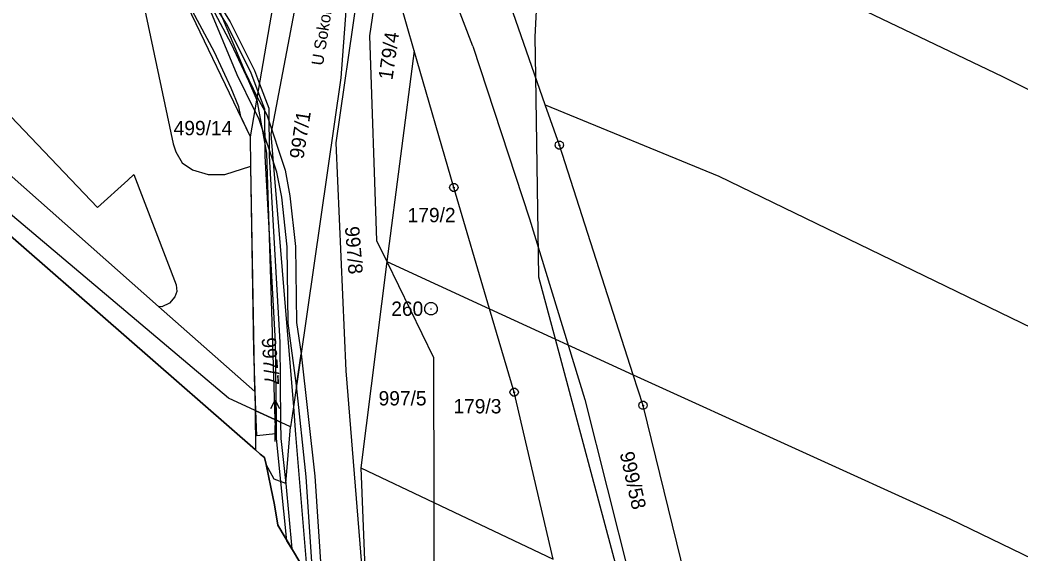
# Model space of a CAD drawing. Extents: x -755359 to -754474, y -1162585 to -1161655.
# Drawn here: x -755164.4 to -755045.7, y -1162495.1 to -1162431.7 of the extents above; entities that cross this region are included whole.
import ezdxf

# ---------------------------------------------------------------- set-up
doc = ezdxf.new("R2010")
doc.units = 0
for name, color, linetype in [('Vrstva 1', 7, 'Continuous'), ('Vrstva 11', 7, 'Continuous'), ('Vrstva 13', 7, 'Continuous'), ('Vrstva 2', 7, 'Continuous'), ('Vrstva 4', 7, 'Continuous'), ('Vrstva 6', 7, 'Continuous'), ('Vrstva 7', 7, 'Continuous'), ('Vrstva 8', 7, 'Continuous')]:
    doc.layers.add(name, color=color, linetype=linetype)

msp = doc.modelspace()

# ---------------------------------------------------------------- linework, layer by layer
at = {"layer": 'Vrstva 1'}
for p, q in [((-755208.3, -1162398.17), (-755155.2, -1162454)), ((-755137.03, -1162445.6), (-755132.49, -1162419.21)), ((-755125.01, -1162420.99), (-755126.31, -1162438.59)), ((-755102.04, -1162441.81), (-755109.07, -1162421.69)), ((-755121.39, -1162423.55), (-755122.9, -1162433.61)), ((-755117.59, -1162435.42), (-755120.28, -1162426.16)), ((-755047.73, -1162438.47), (-755073.63, -1162426.1)), ((-755149.93, -1162428.84), (-755146.21, -1162446.45)), ((-755137.03, -1162445.6), (-755145.43, -1162428.12)), ((-755122.9, -1162433.61), (-755122.06, -1162457.89)), ((-755117.59, -1162435.42), (-755120.84, -1162460.4)), ((-755112.89, -1162451.61), (-755117.59, -1162435.42)), ((-755126.31, -1162438.59), (-755131.94, -1162477.65)), ((-754970.94, -1162477.7), (-755047.73, -1162438.47)), ((-755177.29, -1162439.75), (-755147.93, -1162465.72)), ((-755102.04, -1162441.81), (-755081.44, -1162450.28)), ((-755100.37, -1162446.59), (-755102.04, -1162441.81)), ((-755178.31, -1162446.22), (-755136.42, -1162482.75)), ((-755146.21, -1162446.45), (-755145.88, -1162447.38)), ((-755136.97, -1162449.09), (-755137.03, -1162445.6)), ((-755091.61, -1162473.83), (-755100.37, -1162446.59)), ((-755139.64, -1162476.61), (-755175.06, -1162446.75)), ((-755145.88, -1162447.38), (-755145.15, -1162448.68)), ((-755145.15, -1162448.68), (-755143.92, -1162449.51)), ((-755151.6, -1162450.76), (-755150.88, -1162450.09)), ((-755150.88, -1162450.09), (-755145.86, -1162463.15)), ((-755143.92, -1162449.51), (-755142.03, -1162450.09)), ((-755142.03, -1162450.09), (-755140.07, -1162450.08)), ((-755140.07, -1162450.08), (-755136.97, -1162449.09)), ((-755136.53, -1162475.81), (-755136.97, -1162449.09)), ((-755155.2, -1162454), (-755151.6, -1162450.76)), ((-755081.44, -1162450.28), (-754979.63, -1162499.65)), ((-755108.65, -1162466), (-755112.89, -1162451.61)), ((-755122.06, -1162457.89), (-755120.84, -1162460.4)), ((-755120.84, -1162460.4), (-755123.93, -1162484.86)), ((-755120.84, -1162460.4), (-755108.65, -1162466)), ((-755120.84, -1162460.4), (-755115.31, -1162471.78)), ((-755145.86, -1162463.15), (-755145.78, -1162463.97)), ((-755145.78, -1162463.97), (-755146.01, -1162464.59)), ((-755146.63, -1162465.33), (-755147.53, -1162465.77)), ((-755146.01, -1162464.59), (-755146.63, -1162465.33)), ((-755147.53, -1162465.77), (-755147.93, -1162465.72)), ((-755147.93, -1162465.72), (-755136.53, -1162475.81)), ((-755108.65, -1162466), (-755091.61, -1162473.83)), ((-755105.74, -1162475.9), (-755108.65, -1162466)), ((-755115.31, -1162471.78), (-755115.28, -1162488.97)), ((-755091.61, -1162473.83), (-755054.02, -1162490.91)), ((-755090.44, -1162477.46), (-755091.61, -1162473.83)), ((-755136.53, -1162475.81), (-755136.49, -1162478.06)), ((-755101.11, -1162495.7), (-755105.74, -1162475.9)), ((-755136.49, -1162478.06), (-755139.64, -1162476.61)), ((-755083.94, -1162503.85), (-755090.44, -1162477.46)), ((-755132.28, -1162480), (-755136.49, -1162478.06)), ((-755136.49, -1162478.06), (-755136.42, -1162482.75)), ((-755131.94, -1162477.65), (-755132.28, -1162480)), ((-755132.85, -1162486.73), (-755132.28, -1162480)), ((-755136.42, -1162482.75), (-755135.89, -1162483.24)), ((-755135.89, -1162483.24), (-755135.35, -1162483.65)), ((-755135.35, -1162483.65), (-755135.17, -1162484.49)), ((-755135.17, -1162484.49), (-755134.62, -1162487.15)), ((-755134.2, -1162486.2), (-755135.17, -1162484.49)), ((-755123.93, -1162484.86), (-755123.19, -1162503.76)), ((-755123.93, -1162484.86), (-755115.28, -1162488.97)), ((-755132.85, -1162486.73), (-755134.2, -1162486.2)), ((-755134.62, -1162487.15), (-755134.18, -1162489.26)), ((-755134.18, -1162489.26), (-755133.78, -1162491.69)), ((-755115.28, -1162488.97), (-755101.11, -1162495.7)), ((-755115.28, -1162488.97), (-755115.23, -1162517.45)), ((-755133.78, -1162491.69), (-755130.29, -1162497.54)), ((-755054.02, -1162490.91), (-754988.9, -1162522.63))]:
    msp.add_line(p, q, dxfattribs=at)
at = {"layer": 'Vrstva 11'}
for p, q in [((-755102.77, -1162423.32), (-755103.29, -1162433.76)), ((-755103.29, -1162433.76), (-755103.22, -1162438.44)), ((-755103.22, -1162438.44), (-755102.85, -1162462.21)), ((-755136.42, -1162482.75), (-755178.31, -1162446.22)), ((-755102.85, -1162462.21), (-755100.87, -1162469.57)), ((-755100.87, -1162469.57), (-755092.8, -1162499.65)), ((-755135.89, -1162483.24), (-755136.42, -1162482.75)), ((-755135.35, -1162483.65), (-755135.89, -1162483.24)), ((-755135.17, -1162484.49), (-755135.35, -1162483.65)), ((-755134.62, -1162487.15), (-755135.17, -1162484.49)), ((-755134.18, -1162489.26), (-755134.62, -1162487.15)), ((-755133.78, -1162491.69), (-755134.18, -1162489.26)), ((-755130.29, -1162497.54), (-755133.78, -1162491.69))]:
    msp.add_line(p, q, dxfattribs=at)
at = {"layer": 'Vrstva 13'}
for p, q in [((-755148.65, -1162416.97), (-755139.33, -1162434.57)), ((-755141.31, -1162435.57), (-755150.61, -1162418.01)), ((-755139.87, -1162432.2), (-755144.55, -1162424.83)), ((-755143.95, -1162424.85), (-755139.43, -1162431.96)), ((-755138.6, -1162438.25), (-755142.13, -1162429.79)), ((-755141.25, -1162429.33), (-755137.68, -1162437.85)), ((-755137, -1162437.95), (-755139.87, -1162432.2)), ((-755139.43, -1162431.96), (-755136.54, -1162437.75)), ((-755139.33, -1162434.57), (-755137.26, -1162438.95)), ((-755139.3, -1162439.85), (-755141.31, -1162435.57)), ((-755136.5, -1162442.51), (-755138.6, -1162438.25)), ((-755137.68, -1162437.85), (-755136.22, -1162440.9)), ((-755136.11, -1162440.27), (-755137, -1162437.95)), ((-755136.54, -1162437.75), (-755135.95, -1162439.3)), ((-755137.26, -1162438.95), (-755136.28, -1162441.25)), ((-755135.95, -1162439.3), (-755134.83, -1162442.21)), ((-755138.39, -1162442.06), (-755139.3, -1162439.85)), ((-755135.33, -1162442.31), (-755136.11, -1162440.27)), ((-755136.28, -1162441.25), (-755135.14, -1162447.54)), ((-755136.22, -1162440.9), (-755135.1, -1162443.01)), ((-755138.19, -1162443.19), (-755138.39, -1162442.06)), ((-755136.02, -1162443.41), (-755136.5, -1162442.51)), ((-755135.3, -1162447.87), (-755135.33, -1162442.31)), ((-755135.1, -1162443.01), (-755132.93, -1162449.56)), ((-755134.83, -1162442.21), (-755134.8, -1162447.85)), ((-755137.03, -1162445.6), (-755138.19, -1162443.19)), ((-755133.91, -1162449.8), (-755136.02, -1162443.41)), ((-755136.97, -1162449.09), (-755137.03, -1162445.6)), ((-755135.14, -1162447.54), (-755134.54, -1162466.28)), ((-755134.04, -1162469.97), (-755135.3, -1162447.87)), ((-755134.8, -1162447.85), (-755133.54, -1162469.95)), ((-755136.61, -1162470.94), (-755136.97, -1162449.09)), ((-755133.32, -1162452.76), (-755133.91, -1162449.8)), ((-755132.93, -1162449.56), (-755132.34, -1162452.6)), ((-755132.67, -1162458.66), (-755133.32, -1162452.76)), ((-755132.34, -1162452.6), (-755131.67, -1162458.6)), ((-755132.56, -1162467.72), (-755132.67, -1162458.66)), ((-755131.67, -1162458.6), (-755131.56, -1162467.64)), ((-755134.54, -1162466.28), (-755134.12, -1162479.15)), ((-755131.57, -1162475.1), (-755132.56, -1162467.72)), ((-755131.56, -1162467.64), (-755131.03, -1162471.33)), ((-755133.95, -1162479.23), (-755134.04, -1162469.97)), ((-755133.54, -1162469.95), (-755133.45, -1162479.46)), ((-755136.38, -1162478.11), (-755136.61, -1162470.94)), ((-755131.03, -1162471.33), (-755131.57, -1162475.1)), ((-755131.57, -1162475.1), (-755131.03, -1162471.33)), ((-755131.03, -1162471.33), (-755129.4, -1162485.84)), ((-755130.4, -1162485.92), (-755131.57, -1162475.1)), ((-755136.28, -1162481.07), (-755136.38, -1162478.11)), ((-755136.38, -1162478.11), (-755134.12, -1162479.15)), ((-755134.12, -1162479.15), (-755136.38, -1162478.11)), ((-755134.12, -1162479.15), (-755134.07, -1162480.84)), ((-755133.93, -1162481.4), (-755133.95, -1162479.23)), ((-755133.95, -1162479.23), (-755133.45, -1162479.46)), ((-755133.45, -1162479.46), (-755133.95, -1162479.23)), ((-755133.45, -1162479.46), (-755133.43, -1162481.4)), ((-755134.07, -1162480.84), (-755136.28, -1162481.07)), ((-755133.41, -1162486.51), (-755133.93, -1162481.4)), ((-755133.43, -1162481.4), (-755132.85, -1162486.73)), ((-755132.7, -1162493.51), (-755133.41, -1162486.51)), ((-755132.85, -1162486.73), (-755132.11, -1162494.48)), ((-755129.57, -1162498.75), (-755130.4, -1162485.92)), ((-755129.4, -1162485.84), (-755128.4, -1162500.72)), ((-755132.11, -1162494.48), (-755132.7, -1162493.51))]:
    msp.add_line(p, q, dxfattribs=at)
at = {"layer": 'Vrstva 4'}
for p, q in [((-755130.55, -1162424.05), (-755134.62, -1162445.29)), ((-755126.85, -1162446.31), (-755124.28, -1162428.44)), ((-755134.62, -1162445.29), (-755131.94, -1162477.65)), ((-755125.67, -1162473.35), (-755126.85, -1162446.31)), ((-755123.19, -1162503.76), (-755125.67, -1162473.35)), ((-755131.94, -1162477.65), (-755131.67, -1162480.93)), ((-755131.67, -1162480.93), (-755130.29, -1162497.54))]:
    msp.add_line(p, q, dxfattribs=at)
at = {"layer": 'Vrstva 6'}
for p, q in [((-755110.65, -1162434.84), (-755118.44, -1162414.3)), ((-755110.65, -1162434.84), (-755103.9, -1162455.32)), ((-755103.9, -1162455.32), (-755097.36, -1162476.75)), ((-755097.36, -1162476.75), (-755091.92, -1162498.32))]:
    msp.add_line(p, q, dxfattribs=at)
at = {"layer": 'Vrstva 7'}
for p in [(-755134.1, -1162476.84), (-755134.1, -1162481.74)]:
    msp.add_line(p, (-755134.1, -1162479.84), dxfattribs=at)
msp.add_lwpolyline([(-755134.6, -1162477.84), (-755134.1, -1162476.84), (-755133.6, -1162477.84)], dxfattribs=at)
at = {"layer": 'Vrstva 8'}
for p, q in [((-755100.49, -1162446.59), (-755100.25, -1162446.59)), ((-755113.01, -1162451.61), (-755112.77, -1162451.61)), ((-755115.65, -1162465.99), (-755115.55, -1162465.99)), ((-755105.86, -1162475.9), (-755105.62, -1162475.9)), ((-755090.56, -1162477.46), (-755090.32, -1162477.46))]:
    msp.add_line(p, q, dxfattribs=at)
for points in [[(-755100.22, -1162446.11), (-755099.97, -1162446.29), (-755099.87, -1162446.58), (-755099.97, -1162446.87), (-755100.22, -1162447.05), (-755100.53, -1162447.05), (-755100.78, -1162446.87), (-755100.88, -1162446.58), (-755100.78, -1162446.29), (-755100.53, -1162446.11)], [(-755112.74, -1162451.13), (-755112.49, -1162451.31), (-755112.39, -1162451.6), (-755112.49, -1162451.89), (-755112.74, -1162452.07), (-755113.05, -1162452.07), (-755113.3, -1162451.89), (-755113.4, -1162451.6), (-755113.3, -1162451.31), (-755113.05, -1162451.13)], [(-755115.41, -1162465.27), (-755115.07, -1162465.46), (-755114.88, -1162465.8), (-755114.88, -1162466.19), (-755115.07, -1162466.53), (-755115.41, -1162466.72), (-755115.8, -1162466.72), (-755116.14, -1162466.53), (-755116.33, -1162466.19), (-755116.33, -1162465.8), (-755116.14, -1162465.46), (-755115.8, -1162465.27)], [(-755105.59, -1162475.42), (-755105.34, -1162475.6), (-755105.24, -1162475.89), (-755105.34, -1162476.18), (-755105.59, -1162476.36), (-755105.9, -1162476.36), (-755106.15, -1162476.18), (-755106.25, -1162475.89), (-755106.15, -1162475.6), (-755105.9, -1162475.42)], [(-755090.29, -1162476.98), (-755090.04, -1162477.16), (-755089.94, -1162477.45), (-755090.04, -1162477.74), (-755090.29, -1162477.92), (-755090.6, -1162477.92), (-755090.85, -1162477.74), (-755090.95, -1162477.45), (-755090.85, -1162477.16), (-755090.6, -1162476.98)]]:
    msp.add_lwpolyline(points, close=True, dxfattribs=at)

# ---------------------------------------------------------------- texts
at = {"layer": 'Vrstva 2'}
for s, height, rotation, p in [('179/4', 1.7, 81.87567, (-755120.185, -1162438.931)), ('997/1', 1.7, 81.01623, (-755130.743, -1162448.306)), ('997/8', 1.7, 274.50408, (-755125.821, -1162456.287)), ('997/7', 0.1, 89.09494, (-755134.1, -1162481.726)), ('999/58', 1.7, 282.58278, (-755093.218, -1162483.152))]:
    msp.add_text(s, height=height, rotation=rotation, dxfattribs=at).set_placement(p)
for s, p in [('499/14', (-755146.144, -1162445.41)), ('179/2', (-755118.377, -1162455.73)), ('997/5', (-755121.823, -1162477.47)), ('179/3', (-755112.937, -1162478.41))]:
    msp.add_text(s, height=1.7, dxfattribs=at).set_placement(p)
at = {"layer": 'Vrstva 7'}
for s, height, rotation, p in [('U Sokolovny', 1.4, 81.01623, (-755128.424, -1162437.217)), ('997/7', 1.7, 273.98842, (-755135.709, -1162469.461))]:
    msp.add_text(s, height=height, rotation=rotation, dxfattribs=at).set_placement(p)
at = {"layer": 'Vrstva 8'}
msp.add_text('260', height=1.7, dxfattribs=at).set_placement((-755120.318, -1162466.84))

doc.saveas('drawing.dxf')
